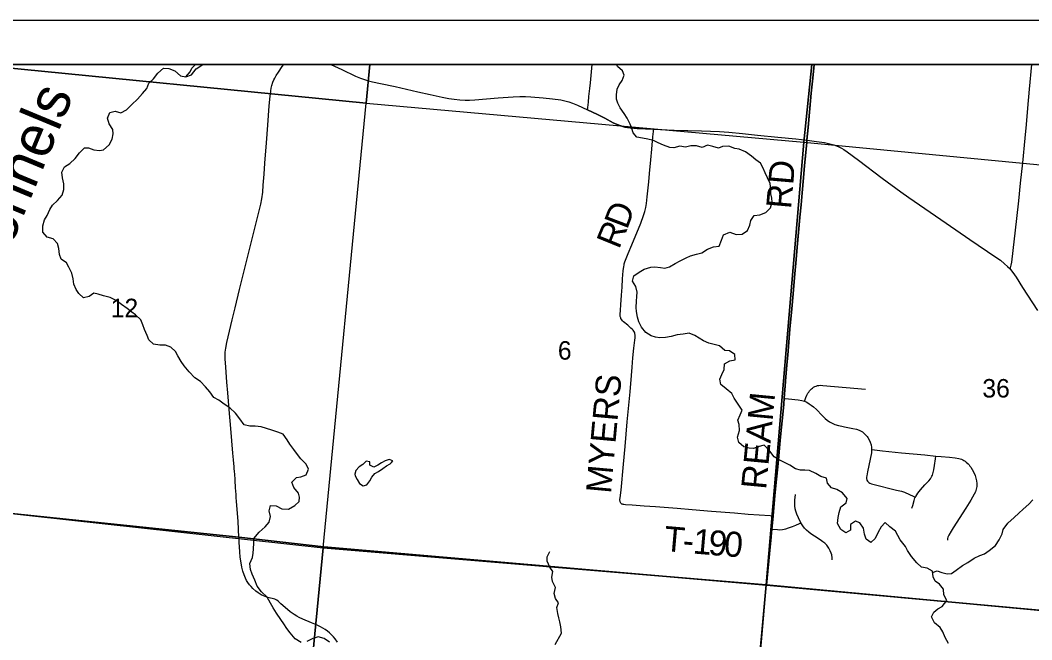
# Model space of a CAD drawing. Extents: x 831 to 1552, y 430 to 870.
# Drawn here: x 1297.57 to 1343.42, y 760.87 to 788.94 of the extents above; entities that cross this region are included whole.
import ezdxf

# ---------------------------------------------------------------- set-up
doc = ezdxf.new("R2010")
doc.units = 0
for name, color, linetype in [('GM_X_Corporation', 7, 'Continuous'), ('GM_X_County_Road', 7, 'Continuous'), ('GM_X_County_Road_Text', 7, 'Continuous'), ('GM_X_Minor_Lake', 7, 'Continuous'), ('GM_X_Minor_River', 7, 'Continuous'), ('GM_X_Minor_River_Text', 7, 'Continuous'), ('GM_X_Section_Text', 7, 'Continuous'), ('GM_X_Township_Road', 7, 'Continuous'), ('GM_X_Township_Road_Text', 7, 'Continuous'), ('SH_Data', 7, 'Continuous')]:
    doc.layers.add(name, color=color, linetype=linetype)

msp = doc.modelspace()

# ---------------------------------------------------------------- linework, layer by layer
at = {"layer": 'GM_X_Corporation'}
for points in [[(1280.784, 768.299), (1307.479, 765.521), (1311.322, 765.075), (1331.394, 763.348), (1331.53, 764.765), (1331.589, 765.36), (1331.636, 765.884), (1331.66, 766.164), (1331.69, 766.478), (1331.777, 767.401), (1331.851, 768.142), (1331.902, 768.697), (1331.95, 769.191), (1331.986, 769.562), (1332.036, 770.056), (1332.152, 771.227), (1332.177, 771.535), (1332.199, 771.815), (1332.26, 772.586), (1332.318, 773.329), (1332.355, 773.762), (1332.457, 774.938), (1332.539, 775.865), (1332.602, 776.546), (1332.668, 777.288), (1332.741, 778.092), (1332.807, 778.835), (1332.849, 779.33), (1332.91, 780.011), (1332.959, 780.567), (1333.006, 781.124), (1333.07, 781.804), (1333.123, 782.361), (1333.166, 782.793), (1333.219, 783.412), (1333.229, 783.519), (1333.287, 784.091), (1333.426, 785.638), (1333.49, 786.318), (1333.549, 786.938), (1250.766, 786.938)], [(1386.766, 786.938), (1333.549, 786.938), (1333.49, 786.318), (1333.426, 785.638), (1333.287, 784.091), (1333.229, 783.519), (1333.219, 783.412), (1333.166, 782.793), (1333.123, 782.361), (1333.07, 781.804), (1333.006, 781.124), (1332.959, 780.567), (1332.91, 780.011), (1332.849, 779.33), (1332.807, 778.835), (1332.741, 778.092), (1332.668, 777.288), (1332.602, 776.546), (1332.539, 775.865), (1332.457, 774.938), (1332.355, 773.762), (1332.318, 773.329), (1332.26, 772.586), (1332.199, 771.815), (1332.177, 771.535), (1332.152, 771.227), (1332.036, 770.056), (1331.986, 769.562), (1331.95, 769.191), (1331.902, 768.697), (1331.851, 768.142), (1331.777, 767.401), (1331.69, 766.478), (1331.66, 766.164), (1331.636, 765.884), (1331.589, 765.36), (1331.53, 764.765), (1331.394, 763.348), (1350.173, 761.613)], [(1350.173, 761.613), (1331.394, 763.348), (1311.322, 765.075), (1307.479, 765.521), (1280.784, 768.299)]]:
    msp.add_lwpolyline(points, dxfattribs=at)
for points in [[(1295.453, 786.938), (1293.37, 786.938), (1291.379, 767.224), (1311.293, 765.037), (1313.248, 785.183)], [(1313.412, 786.938), (1295.453, 786.938), (1313.248, 785.183)], [(1333.448, 786.938), (1313.412, 786.938), (1313.248, 785.183), (1333.094, 783.414)], [(1353.25, 786.938), (1333.448, 786.938), (1333.094, 783.414), (1352.786, 781.526)], [(1313.248, 785.183), (1333.094, 783.414), (1331.382, 763.355), (1311.293, 765.037)], [(1333.094, 783.414), (1352.786, 781.526), (1350.153, 761.603), (1331.382, 763.355)], [(1291.379, 767.224), (1311.293, 765.037), (1309.391, 745.383), (1289.554, 747.22)], [(1311.293, 765.037), (1331.382, 763.355), (1329.567, 743.48), (1309.391, 745.383)], [(1331.382, 763.355), (1350.153, 761.603), (1348.747, 741.721), (1329.567, 743.48)]]:
    msp.add_lwpolyline(points, close=True, dxfattribs=at)
at = {"layer": 'GM_X_County_Road'}
for points in [[(1308.922, 785.705), (1308.926, 785.736), (1308.947, 785.857), (1308.976, 785.977), (1309.025, 786.129), (1309.067, 786.235), (1309.106, 786.318), (1309.167, 786.428), (1309.267, 786.583), (1309.446, 786.835), (1309.515, 786.938)], [(1311.646, 786.938), (1312.15, 786.699), (1312.769, 786.408), (1312.998, 786.311), (1313.174, 786.246), (1313.353, 786.192), (1313.535, 786.146), (1313.9, 786.069), (1314.568, 785.929), (1315.597, 785.691), (1316.142, 785.569), (1316.689, 785.45), (1316.994, 785.391), (1317.241, 785.355), (1317.489, 785.33), (1317.738, 785.316), (1317.925, 785.317), (1318.174, 785.331), (1319.227, 785.415), (1319.908, 785.47), (1320.218, 785.483), (1320.465, 785.484), (1320.712, 785.471), (1321.269, 785.42), (1321.701, 785.374), (1322.069, 785.324), (1322.252, 785.291), (1322.43, 785.245), (1322.604, 785.183), (1322.832, 785.085), (1323.286, 784.885)], [(1333.234, 783.508), (1333.292, 784.081), (1333.43, 785.628), (1333.494, 786.308), (1333.555, 786.938)], [(1307.485, 765.491), (1307.484, 765.511), (1307.441, 766.222), (1307.37, 767.153), (1307.359, 767.302), (1307.35, 767.444), (1307.339, 767.602), (1307.328, 767.749), (1307.327, 767.805), (1307.323, 767.875), (1307.317, 767.973), (1307.313, 768.054), (1307.305, 768.16), (1307.292, 768.335), (1307.277, 768.526), (1307.272, 768.59), (1307.263, 768.706), (1307.238, 769.017), (1307.209, 769.326), (1307.16, 769.882), (1307.113, 770.439), (1307.043, 771.306), (1306.98, 772.049), (1306.939, 772.544), (1306.88, 773.224), (1306.856, 773.595), (1306.855, 773.78), (1306.863, 773.903), (1306.886, 774.086), (1306.934, 774.329), (1307.175, 775.357), (1307.306, 775.9), (1307.508, 776.744), (1307.594, 777.107), (1307.711, 777.589), (1307.944, 778.491), (1308.127, 779.214), (1308.265, 779.755), (1308.403, 780.298), (1308.471, 780.602), (1308.515, 780.847), (1308.557, 781.155), (1308.587, 781.465), (1308.621, 781.961), (1308.658, 782.456), (1308.727, 783.386), (1308.795, 784.19), (1308.858, 785.057), (1308.898, 785.49), (1308.922, 785.705)], [(1323.286, 784.885), (1323.733, 784.67), (1324.062, 784.497), (1324.449, 784.296), (1324.619, 784.219), (1324.795, 784.152), (1324.975, 784.098), (1325.098, 784.072), (1325.222, 784.056), (1325.532, 784.03), (1326.275, 783.996)], [(1326.275, 783.996), (1327.209, 783.964), (1327.83, 783.945), (1328.451, 783.923), (1329.257, 783.891), (1329.69, 783.86), (1330.308, 783.802), (1330.988, 783.734), (1331.915, 783.645), (1332.719, 783.566), (1333.234, 783.508)], [(1332.204, 771.805), (1332.265, 772.576), (1332.323, 773.318), (1332.359, 773.751), (1332.461, 774.927), (1332.544, 775.855), (1332.606, 776.535), (1332.673, 777.278), (1332.746, 778.082), (1332.811, 778.824), (1332.854, 779.319), (1332.915, 780), (1332.963, 780.557), (1333.01, 781.114), (1333.075, 781.794), (1333.128, 782.35), (1333.17, 782.783), (1333.223, 783.401), (1333.234, 783.508)], [(1333.234, 783.508), (1333.662, 783.448), (1334.03, 783.391), (1334.272, 783.341), (1334.451, 783.292), (1334.567, 783.252), (1334.68, 783.203), (1334.788, 783.146), (1334.893, 783.081), (1335.044, 782.974), (1335.559, 782.595), (1336.641, 781.789), (1337.487, 781.158), (1337.841, 780.904), (1338.815, 780.237), (1339.532, 779.745), (1340.61, 779.01), (1341.793, 778.208), (1341.994, 778.064), (1342.186, 777.908), (1342.323, 777.783), (1342.433, 777.667)], [(1342.433, 777.667), (1342.45, 777.649), (1342.565, 777.505), (1342.705, 777.301), (1343.005, 776.829), (1343.673, 775.781)], [(1331.814, 767.722), (1331.855, 768.132), (1331.906, 768.687), (1331.954, 769.18), (1331.991, 769.551), (1332.041, 770.045), (1332.157, 771.217), (1332.181, 771.524), (1332.204, 771.805)], [(1331.695, 766.468), (1331.782, 767.39), (1331.814, 767.722)], [(1331.64, 765.874), (1331.665, 766.153), (1331.695, 766.468)], [(1331.398, 763.338), (1331.535, 764.754), (1331.594, 765.349), (1331.64, 765.874)], [(1311.95, 760.751), (1311.842, 760.905), (1311.763, 761.002), (1311.678, 761.094), (1311.586, 761.18), (1311.49, 761.26), (1311.388, 761.334), (1311.282, 761.4), (1311.171, 761.458), (1311.001, 761.537), (1310.771, 761.632), (1310.377, 761.797), (1310.215, 761.872), (1310.105, 761.935), (1309.983, 762.009), (1309.796, 762.139), (1309.472, 762.414), (1309.387, 762.494), (1309.305, 762.569), (1309.256, 762.613), (1309.197, 762.657), (1309.146, 762.685), (1309.105, 762.7), (1308.792, 762.782), (1308.667, 762.821), (1308.591, 762.852), (1308.495, 762.903), (1308.36, 762.988), (1308.247, 763.071), (1308.112, 763.189), (1308.031, 763.278), (1307.964, 763.359), (1307.887, 763.469), (1307.824, 763.56), (1307.779, 763.657), (1307.72, 763.802), (1307.665, 763.969), (1307.616, 764.158), (1307.578, 764.359), (1307.54, 764.604), (1307.519, 764.846), (1307.497, 765.289), (1307.485, 765.491)], [(1330.507, 753.392), (1330.529, 753.708), (1330.657, 755.129), (1330.785, 756.488), (1330.829, 756.982), (1330.891, 757.662), (1331.003, 758.898), (1331.053, 759.454), (1331.11, 760.072), (1331.202, 761.123), (1331.371, 763.04), (1331.398, 763.338)]]:
    msp.add_lwpolyline(points, dxfattribs=at)
at = {"layer": 'GM_X_Minor_Lake'}
for points in [[(1305.081, 786.369), (1305.274, 786.602), (1305.352, 786.76), (1305.514, 786.926), (1305.535, 786.938)], [(1305.081, 786.369), (1305.326, 786.457), (1305.542, 786.735), (1305.802, 786.907), (1305.865, 786.938)], [(1314.399, 768.904), (1314.459, 768.97), (1314.293, 769.033), (1314.11, 768.975), (1313.942, 768.885), (1313.781, 768.773), (1313.59, 768.692), (1313.416, 768.778), (1313.418, 768.93), (1313.244, 768.962), (1313.09, 768.805), (1312.937, 768.708), (1312.783, 768.542), (1312.735, 768.368)], [(1312.735, 768.368), (1312.749, 768.292), (1312.846, 768.124), (1312.95, 767.948), (1313.116, 767.847), (1313.283, 767.89), (1313.415, 768.071), (1313.501, 768.237), (1313.639, 768.395), (1313.808, 768.492), (1313.999, 768.626), (1314.168, 768.746), (1314.336, 768.835), (1314.399, 768.904)]]:
    msp.add_lwpolyline(points, dxfattribs=at)
at = {"layer": 'GM_X_Minor_River'}
for points in [[(1302.79, 775.586), (1302.632, 775.709), (1302.421, 775.872), (1302.158, 776.065), (1301.909, 776.235), (1301.638, 776.382), (1301.342, 776.454), (1301.1, 776.533), (1300.903, 776.574), (1300.696, 776.417), (1300.43, 776.359), (1300.219, 776.552), (1300.108, 776.743), (1300.004, 776.98), (1299.962, 777.223), (1299.912, 777.482), (1299.778, 777.742), (1299.659, 777.941), (1299.418, 778.119), (1299.345, 778.325), (1299.31, 778.591), (1299.252, 778.827), (1299.065, 779.035), (1298.793, 779.114), (1298.598, 779.329), (1298.594, 779.625), (1298.673, 779.898), (1298.79, 780.094), (1298.914, 780.358), (1299.023, 780.562), (1299.261, 780.772), (1299.462, 781.013), (1299.541, 781.27), (1299.544, 781.528), (1299.487, 781.795), (1299.452, 782.061), (1299.577, 782.303), (1299.814, 782.444), (1300.052, 782.669), (1300.253, 782.925), (1300.476, 783.15), (1300.666, 783.163), (1300.908, 783.069), (1301.158, 783.036), (1301.349, 783.071), (1301.594, 783.296), (1301.742, 783.545), (1301.783, 783.788), (1301.77, 783.986), (1301.606, 784.246), (1301.526, 784.505), (1301.635, 784.762), (1301.872, 784.82), (1302.121, 784.741), (1302.389, 784.882), (1302.62, 785.122), (1302.889, 785.362), (1303.105, 785.618), (1303.305, 785.851), (1303.392, 786.093), (1303.607, 786.288), (1303.8, 786.536), (1304.061, 786.768), (1304.311, 786.758), (1304.576, 786.641), (1304.831, 786.425), (1305.081, 786.369), (1305.326, 786.457), (1305.542, 786.735), (1305.802, 786.907), (1305.865, 786.938)], [(1331.224, 782.268), (1331.127, 782.459), (1330.909, 782.606), (1330.714, 782.775), (1330.442, 782.976), (1330.148, 783.101), (1329.958, 783.126), (1329.686, 783.228), (1329.405, 783.217), (1329.214, 783.143), (1328.964, 783.222), (1328.722, 783.27), (1328.477, 783.167), (1328.228, 783.246), (1327.969, 783.249), (1327.725, 783.184), (1327.468, 783.225), (1327.201, 783.16), (1327.011, 783.177), (1326.731, 783.279), (1326.482, 783.381), (1326.271, 783.482), (1326.013, 783.554), (1325.77, 783.587), (1325.52, 783.643), (1325.356, 783.835), (1325.297, 784.026), (1325.209, 784.224), (1325.075, 784.507), (1324.949, 784.706), (1324.754, 784.974), (1324.651, 785.173), (1324.6, 785.364), (1324.594, 785.554), (1324.628, 785.811), (1324.714, 786.008), (1324.846, 786.204), (1324.94, 786.453), (1324.874, 786.644), (1324.641, 786.844), (1324.593, 786.938)], [(1334.582, 767.679), (1334.34, 767.751), (1334.161, 767.958), (1334.118, 768.194), (1333.853, 768.258), (1333.634, 768.405), (1333.34, 768.53), (1333.127, 768.555), (1332.937, 768.558), (1332.702, 768.614), (1332.454, 768.776), (1331.941, 769.041), (1331.737, 769.149), (1331.543, 769.418), (1331.288, 769.679), (1331.006, 769.607), (1330.799, 769.533), (1330.61, 769.55), (1330.36, 769.614), (1330.134, 769.799), (1330.084, 770.043), (1330.164, 770.346), (1330.152, 770.627), (1330.101, 770.818), (1330.203, 771.052), (1330.297, 771.264), (1329.924, 771.815), (1329.82, 772.022), (1329.564, 772.23), (1329.324, 772.43), (1329.281, 772.682), (1329.368, 772.886), (1329.469, 773.112), (1329.488, 773.37), (1329.732, 773.504), (1329.968, 773.555), (1329.964, 773.798), (1329.715, 773.953), (1329.51, 773.97), (1329.262, 774.179), (1328.967, 774.266), (1328.777, 774.306), (1328.543, 774.415), (1328.347, 774.531), (1328.144, 774.648), (1327.894, 774.757), (1327.613, 774.707), (1327.346, 774.68), (1327.08, 774.615), (1326.821, 774.565), (1326.555, 774.553), (1326.365, 774.578), (1326.168, 774.641), (1325.919, 774.789), (1325.733, 775.034), (1325.607, 775.279), (1325.548, 775.484), (1325.506, 775.736), (1325.493, 775.926), (1325.497, 776.214), (1325.522, 776.419), (1325.532, 776.624), (1325.474, 776.876), (1325.326, 777.121), (1325.382, 777.355), (1325.627, 777.519), (1325.849, 777.654), (1326.146, 777.749), (1326.336, 777.762), (1326.594, 777.736), (1326.784, 777.703), (1327.005, 777.761), (1327.257, 777.918), (1327.487, 778.036), (1327.747, 778.178), (1327.945, 778.259), (1328.227, 778.331), (1328.464, 778.397), (1328.724, 778.568), (1328.991, 778.664), (1329.242, 778.706), (1329.352, 778.979), (1329.446, 779.221), (1329.729, 779.331), (1330.024, 779.236), (1330.297, 779.241), (1330.535, 779.413), (1330.644, 779.647), (1330.685, 779.867), (1330.84, 780.093), (1331.091, 780.127), (1331.366, 780.231), (1331.581, 780.441), (1331.645, 780.691), (1331.632, 780.881), (1331.589, 781.079), (1331.584, 781.276), (1331.557, 781.542), (1331.446, 781.802), (1331.327, 782.024), (1331.224, 782.268)], [(1308.092, 764.602), (1308.124, 764.791), (1308.134, 764.989), (1308.153, 765.247), (1308.163, 765.46), (1308.402, 765.738), (1308.671, 765.985), (1308.856, 766.196), (1308.905, 766.446), (1308.847, 766.713), (1308.919, 766.948), (1309.162, 766.937), (1309.433, 766.797), (1309.73, 766.786), (1310.013, 766.95), (1310.213, 767.137), (1310.223, 767.327), (1310.187, 767.517), (1309.977, 767.771), (1309.882, 768.015), (1310.089, 768.218), (1310.287, 768.246), (1310.532, 768.342), (1310.641, 768.591), (1310.522, 768.828), (1310.29, 769.067), (1310.133, 769.266), (1309.976, 769.481), (1309.789, 769.734), (1309.67, 769.933), (1309.484, 770.186), (1309.242, 770.28), (1308.969, 770.367), (1308.492, 770.509), (1308.212, 770.543), (1307.976, 770.546), (1307.719, 770.61), (1307.517, 770.871), (1307.323, 771.131), (1307.075, 771.37), (1306.811, 771.548), (1306.57, 771.718), (1306.344, 771.85), (1306.157, 772.103), (1305.963, 772.326), (1305.738, 772.564), (1305.489, 772.742), (1305.219, 773.011), (1305.002, 773.272), (1304.86, 773.479), (1304.712, 773.731), (1304.608, 773.923), (1304.39, 774.13), (1304.148, 774.209), (1303.89, 774.22), (1303.609, 774.262), (1303.391, 774.454), (1303.318, 774.66), (1303.2, 774.92), (1303.126, 775.134), (1303.031, 775.37), (1302.79, 775.586)], [(1339.646, 760.704), (1339.497, 760.972), (1339.394, 761.231), (1339.26, 761.43), (1339.004, 761.639), (1338.871, 761.899), (1338.972, 762.125), (1339.164, 762.268), (1339.355, 762.372), (1339.571, 762.643), (1339.438, 762.903), (1339.418, 763.154), (1339.239, 763.391), (1339.043, 763.523), (1338.947, 763.714), (1338.92, 763.98), (1338.678, 764.105), (1338.42, 764.153), (1338.203, 764.354), (1337.971, 764.638), (1337.784, 764.906), (1337.688, 765.097), (1337.456, 765.388), (1337.352, 765.587), (1337.248, 765.794), (1336.992, 765.987), (1336.774, 766.179), (1336.597, 765.984), (1336.45, 765.735), (1336.317, 765.463), (1336.125, 765.275), (1335.914, 765.429), (1335.841, 765.658), (1335.791, 765.925), (1335.62, 766.17), (1335.423, 766.241), (1335.208, 766.084), (1335.197, 765.826), (1334.991, 765.706), (1334.757, 765.869), (1334.609, 766.129), (1334.65, 766.41), (1334.683, 766.637), (1334.763, 766.895), (1335.008, 767.066), (1335.056, 767.271), (1334.846, 767.524), (1334.582, 767.679)], [(1338.926, 763.921), (1339.132, 763.985), (1339.337, 763.922), (1339.587, 763.851), (1339.777, 763.871), (1339.999, 764.021), (1340.275, 764.238), (1340.52, 764.364), (1340.803, 764.558), (1341.071, 764.692), (1341.269, 764.766), (1341.492, 764.915), (1341.775, 765.14), (1341.938, 765.396), (1342.078, 765.668), (1342.119, 765.857), (1342.328, 766.151), (1342.62, 766.414), (1342.827, 766.601), (1343.034, 766.781), (1343.28, 767.014), (1343.465, 767.209)], [(1321.815, 760.659), (1322.095, 761.172), (1322.068, 761.454), (1322.025, 761.674), (1321.982, 761.865), (1321.931, 762.063), (1321.897, 762.33), (1321.96, 762.534), (1321.833, 762.733), (1321.776, 762.962), (1321.832, 763.235), (1321.691, 763.51), (1321.663, 763.708), (1321.704, 763.958), (1321.57, 764.158), (1321.452, 764.433), (1321.447, 764.623), (1321.579, 764.872)], [(1310.307, 760.736), (1310.035, 760.915), (1309.803, 761.176), (1309.654, 761.383), (1309.512, 761.582), (1309.378, 761.789), (1309.184, 762.065), (1309.035, 762.318), (1308.909, 762.524), (1308.76, 762.8), (1308.505, 763.038), (1308.311, 763.292), (1308.208, 763.566), (1308.082, 763.834), (1308.001, 764.048), (1307.974, 764.322), (1308.092, 764.602)], [(1311.583, 760.751), (1311.342, 760.929), (1311.077, 761.001), (1310.826, 760.928), (1310.558, 760.787)]]:
    msp.add_lwpolyline(points, dxfattribs=at)
at = {"layer": 'GM_X_Township_Road'}
for points in [[(1323.286, 784.885), (1323.297, 784.991), (1323.321, 785.223), (1323.347, 785.48), (1323.386, 785.85), (1323.413, 786.106), (1323.464, 786.602), (1323.495, 786.938)], [(1342.433, 777.667), (1342.454, 777.726), (1342.473, 777.775), (1342.49, 777.837), (1342.517, 777.977), (1342.737, 779.951), (1342.827, 780.753), (1342.913, 781.555), (1343.01, 782.481), (1343.12, 783.593), (1343.178, 784.211), (1343.243, 784.953), (1343.314, 785.819), (1343.415, 786.938)], [(1326.275, 783.996), (1325.532, 784.03), (1325.222, 784.056), (1325.098, 784.072), (1324.975, 784.098), (1324.795, 784.152), (1324.619, 784.219), (1324.449, 784.296), (1324.062, 784.497), (1323.733, 784.67), (1323.286, 784.885)], [(1331.695, 766.468), (1331.568, 766.476), (1330.567, 766.545), (1329.948, 766.599), (1328.897, 766.684), (1328.032, 766.753), (1327.341, 766.809), (1326.365, 766.886), (1325.854, 766.925), (1325.308, 766.968), (1324.998, 766.985), (1324.935, 766.989), (1324.903, 766.995), (1324.871, 767.004), (1324.843, 767.016), (1324.814, 767.037), (1324.793, 767.059), (1324.774, 767.089), (1324.762, 767.119), (1324.755, 767.152), (1324.753, 767.184), (1324.753, 767.227), (1324.761, 767.299), (1324.809, 767.648), (1324.919, 768.823), (1324.986, 769.627), (1325.084, 770.74), (1325.211, 772.1), (1325.273, 772.842), (1325.303, 773.213), (1325.342, 773.645), (1325.386, 774.077), (1325.427, 774.447), (1325.434, 774.545), (1325.436, 774.632), (1325.437, 774.679), (1325.433, 774.716), (1325.425, 774.757), (1325.409, 774.802), (1325.377, 774.857), (1325.346, 774.896), (1325.308, 774.935), (1325.247, 774.992), (1325.108, 775.115), (1324.919, 775.277), (1324.874, 775.321), (1324.831, 775.369), (1324.798, 775.423), (1324.785, 775.451), (1324.776, 775.482), (1324.769, 775.514), (1324.766, 775.544), (1324.764, 775.608), (1324.773, 775.795), (1324.79, 776.043), (1324.821, 776.475), (1324.848, 776.847), (1324.872, 777.218), (1324.903, 777.59), (1324.926, 777.776), (1324.938, 777.846), (1324.948, 777.9), (1324.974, 777.989), (1325.005, 778.074), (1325.122, 778.365), (1325.288, 778.767), (1325.691, 779.742), (1325.821, 780.091), (1325.878, 780.267), (1325.921, 780.447), (1325.951, 780.63), (1325.99, 780.937), (1326.054, 781.617), (1326.089, 781.988), (1326.145, 782.606), (1326.19, 783.1), (1326.244, 783.656), (1326.267, 783.903), (1326.275, 783.996)], [(1333.12, 771.676), (1333.133, 771.711), (1333.182, 771.851), (1333.225, 771.952), (1333.274, 772.038), (1333.307, 772.091), (1333.345, 772.14), (1333.386, 772.187), (1333.43, 772.231), (1333.478, 772.271), (1333.529, 772.307), (1333.583, 772.338), (1333.64, 772.363), (1333.699, 772.381), (1333.76, 772.394), (1333.822, 772.399), (1333.946, 772.393), (1335, 772.292), (1335.878, 772.216)], [(1332.204, 771.805), (1332.246, 771.801), (1332.391, 771.79), (1332.823, 771.743), (1332.994, 771.714), (1333.12, 771.676)], [(1333.12, 771.676), (1333.228, 771.63), (1333.336, 771.564), (1333.421, 771.499), (1333.519, 771.424), (1333.654, 771.299), (1333.913, 771.029), (1334.048, 770.899), (1334.145, 770.818), (1334.255, 770.735), (1334.365, 770.674), (1334.486, 770.627), (1334.655, 770.572), (1334.806, 770.54), (1334.924, 770.52), (1335.307, 770.445), (1335.475, 770.407), (1335.594, 770.366), (1335.69, 770.323), (1335.75, 770.285), (1335.797, 770.248), (1335.87, 770.171), (1335.912, 770.127), (1335.951, 770.081), (1335.986, 770.031), (1336.047, 769.925), (1336.096, 769.813), (1336.132, 769.696), (1336.154, 769.576), (1336.159, 769.515), (1336.16, 769.486)], [(1336.16, 769.486), (1336.161, 769.454), (1336.158, 769.393), (1336.151, 769.333), (1335.972, 768.482), (1335.935, 768.298), (1335.928, 768.234), (1335.929, 768.167), (1335.945, 768.104), (1335.979, 768.047), (1336.026, 767.999), (1336.081, 767.959), (1336.148, 767.931), (1336.217, 767.911), (1337.292, 767.648), (1337.51, 767.595), (1337.649, 767.549), (1337.88, 767.453), (1338.047, 767.374), (1338.142, 767.329)], [(1336.16, 769.486), (1336.283, 769.471), (1336.652, 769.426), (1337.516, 769.341), (1338.566, 769.242), (1339.065, 769.192)], [(1338.142, 767.329), (1338.157, 767.363), (1338.206, 767.441), (1338.254, 767.513), (1338.37, 767.656), (1338.578, 767.884), (1338.747, 768.067), (1338.823, 768.166), (1338.857, 768.22), (1338.887, 768.275), (1338.913, 768.332), (1338.954, 768.451), (1338.984, 768.572), (1339.016, 768.757), (1339.051, 769.064), (1339.065, 769.192)], [(1339.065, 769.192), (1339.306, 769.168), (1339.687, 769.137), (1339.945, 769.108), (1340.107, 769.076), (1340.226, 769.045), (1340.287, 769.021), (1340.342, 768.99), (1340.397, 768.952), (1340.441, 768.913), (1340.535, 768.832), (1340.577, 768.787), (1340.617, 768.74), (1340.654, 768.69), (1340.718, 768.584), (1340.8, 768.417), (1340.849, 768.303), (1340.888, 768.185), (1340.914, 768.064), (1340.926, 767.941), (1340.926, 767.879), (1340.923, 767.817), (1340.916, 767.755), (1340.903, 767.694), (1340.887, 767.635), (1340.866, 767.577), (1340.814, 767.464), (1340.657, 767.196), (1340.427, 766.828), (1339.862, 765.938), (1339.768, 765.789), (1339.658, 765.609), (1339.62, 765.522), (1339.6, 765.461), (1339.593, 765.382)], [(1332.96, 766.155), (1332.919, 766.231), (1332.842, 766.391), (1332.762, 766.56), (1332.717, 766.688), (1332.688, 766.806), (1332.676, 766.937), (1332.673, 767.064), (1332.682, 767.198), (1332.711, 767.447)], [(1337.979, 766.834), (1338.02, 766.957), (1338.087, 767.183), (1338.125, 767.291), (1338.142, 767.329)], [(1331.64, 765.874), (1331.687, 765.871), (1331.897, 765.86), (1331.996, 765.855), (1332.124, 765.865), (1332.265, 765.895), (1332.395, 765.935), (1332.567, 765.999), (1332.727, 766.062), (1332.896, 766.129), (1332.96, 766.155)], [(1334.367, 764.483), (1334.364, 764.585), (1334.351, 764.71), (1334.329, 764.787), (1334.283, 764.9), (1334.256, 764.955), (1334.226, 765.019), (1334.191, 765.07), (1334.13, 765.15), (1334.041, 765.239), (1333.949, 765.31), (1333.826, 765.388), (1333.563, 765.556), (1333.409, 765.663), (1333.309, 765.739), (1333.202, 765.826), (1333.113, 765.925), (1333.039, 766.024), (1332.979, 766.12), (1332.96, 766.155)]]:
    msp.add_lwpolyline(points, dxfattribs=at)
at = {"layer": 'SH_Data'}
for p, q in [((1248.766, 788.938), (1388.766, 788.938)), ((1250.766, 786.938), (1386.766, 786.938))]:
    msp.add_line(p, q, dxfattribs=at)

# ---------------------------------------------------------------- texts
at = {"layer": 'GM_X_County_Road_Text'}
for s, rotation, p in [('RD', 85.0773, (1332.508, 780.365)), ('REAM', 84.5891, (1331.375, 767.65))]:
    msp.add_text(s, height=1.1364, rotation=rotation, dxfattribs=at).set_placement(p)
at = {"layer": 'GM_X_Minor_River_Text'}
msp.add_text('Donnels', height=1.8941, rotation=67.4595, dxfattribs=at).set_placement((1296.434, 776.961))
at = {"layer": 'GM_X_Section_Text'}
for s, height, p in [('12', 0.8371, (1301.671, 775.483)), ('6', 0.837, (1321.937, 773.56)), ('36', 0.8371, (1341.179, 771.843))]:
    msp.add_text(s, height=height, rotation=0, dxfattribs=at).set_placement(p)
at = {"layer": 'GM_X_Township_Road_Text'}
for s, height, rotation, p in [('D', 1.136, 69.2528, (1325.071, 779.421)), ('R', 1.136, 67.8029, (1324.707, 778.528)), ('MYERS', 1.1364, 84.8567, (1324.342, 767.466)), ('T', 1.136, 355.031, (1326.716, 764.894)), ('1', 1.136, 355.0643, (1328.029, 764.78)), ('9', 1.136, 355.1929, (1328.729, 764.719)), ('0', 1.136, 355.7912, (1329.44, 764.659)), ('-', 1.136, 355.0394, (1327.563, 764.82))]:
    msp.add_text(s, height=height, rotation=rotation, dxfattribs=at).set_placement(p)

doc.saveas('drawing.dxf')
